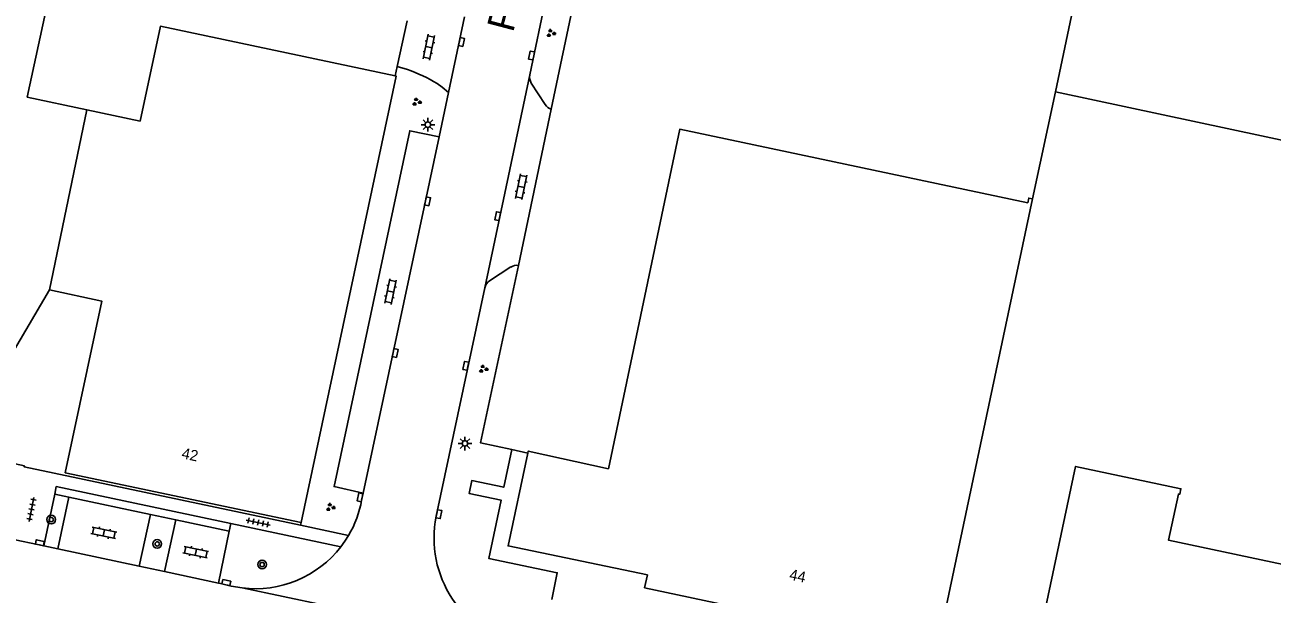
# Model space of a CAD drawing. Extents: x 131000 to 133013, y 393000 to 396501.
# Drawn here: x 131469.8 to 131584.1, y 393541.2 to 393593.5 of the extents above; entities that cross this region are included whole.
import ezdxf

# ---------------------------------------------------------------- set-up
doc = ezdxf.new("R2010")
doc.units = 0
for name, color, linetype in [('gg-afsc-hekwerk', 7, 'Continuous'), ('gg-anno-huisnummerreeks BGT', 7, 'Continuous'), ('gg-anno-openbare ruimte label', 7, 'Continuous'), ('gg-bbg-hoofdgebouw', 7, 'Continuous'), ('gg-bbg-tussenscheiding', 7, 'Continuous'), ('gg-knt-verharding', 7, 'Continuous'), ('gt-grn-groengrens', 7, 'Continuous'), ('gt-grn-vlakafsluiter', 7, 'Continuous'), ('gt-grn-weggrens', 7, 'Continuous'), ('gt-symb-boom', 7, 'Continuous'), ('gt-symb-groenvak', 7, 'Continuous'), ('gt-symb-klinker verharding', 7, 'Continuous'), ('gt-symb-kolk', 7, 'Continuous'), ('gt-symb-lichtmast', 7, 'Continuous'), ('gt-symb-tegel verharding', 7, 'Continuous')]:
    doc.layers.add(name, color=color, linetype=linetype)

# ---------------------------------------------------------------- blocks, each defined once
blk = doc.blocks.new('gt0-GRVAK')
at = {"layer": 'gt-symb-groenvak'}
for p, q in [((-0.11, 0.19), (-0.23, 0.24)), ((-0.18, 0.15), (0.09, 0.15)), ((-0.09, 0.21), (-0.16, 0.32)), ((-0.05, 0.21), (-0.05, 0.39)), ((0, 0.21), (0.06, 0.32)), ((0.02, 0.19), (0.13, 0.24)), ((0.26, -0.05), (0.2, 0.06)), ((0.31, -0.05), (0.31, 0.13)), ((0.35, -0.05), (0.41, 0.06)), ((-0.24, -0.23), (-0.36, -0.18)), ((-0.32, -0.26), (-0.05, -0.26)), ((-0.23, -0.21), (-0.29, -0.09)), ((-0.18, -0.2), (-0.18, -0.02)), ((-0.14, -0.21), (-0.07, -0.09)), ((-0.12, -0.23), (0, -0.18)), ((0.24, -0.07), (0.12, -0.02)), ((0.17, -0.11), (0.44, -0.11)), ((0.37, -0.07), (0.49, -0.02))]:
    blk.add_line(p, q, dxfattribs=at)
blk = doc.blocks.new('gt0-KOLK')
at = {"layer": 'gt-symb-kolk'}
blk.add_lwpolyline([(0, 0), (0.37, 0), (0.37, 0.4), (-0.38, 0.4), (-0.38, 0), (0, 0)], dxfattribs=at)
blk = doc.blocks.new('gt0-LMAST')
at = {"layer": 'gt-symb-lichtmast'}
for p, q in [((-0.18, 0.17), (-0.45, 0.44)), ((-0.01, 0.25), (-0.01, 0.62)), ((0.17, 0.17), (0.44, 0.44)), ((-0.26, 0), (-0.63, 0)), ((-0.18, -0.18), (-0.45, -0.45)), ((-0.01, -0.25), (-0.01, -0.63)), ((0.44, -0.45), (0.17, -0.18)), ((0.24, 0), (0.62, 0))]:
    blk.add_line(p, q, dxfattribs=at)
blk.add_circle((-0.01, 0), 0.25, dxfattribs=at)
blk = doc.blocks.new('gt0-KL1')
at = {"layer": 'gt-symb-klinker verharding'}
for p, q in [((-1.15, 0.3), (1.15, 0.3)), ((-1, -0.3), (-1, 0.3)), ((-0.5, 0.3), (-0.5, 0.45)), ((0, -0.3), (0, 0.3)), ((0.5, 0.3), (0.5, 0.45)), ((1, -0.3), (1, 0.3)), ((-1.15, -0.3), (1.15, -0.3)), ((-0.5, -0.45), (-0.5, -0.3)), ((0.5, -0.45), (0.5, -0.3))]:
    blk.add_line(p, q, dxfattribs=at)
blk = doc.blocks.new('gt0-TEG1')
at = {"layer": 'gt-symb-tegel verharding'}
for p, q in [((-1.12, 0), (1.12, 0)), ((-0.9, -0.25), (-0.9, 0.25)), ((-0.45, -0.25), (-0.45, 0.25)), ((0, -0.25), (0, 0.25)), ((0.45, -0.25), (0.45, 0.25)), ((0.9, -0.25), (0.9, 0.25))]:
    blk.add_line(p, q, dxfattribs=at)
blk = doc.blocks.new('gt0-BOOM')
at = {"layer": 'gt-symb-boom'}
for radius in [0.4, 0.2]:
    blk.add_circle((0, 0), radius, dxfattribs=at)

msp = doc.modelspace()

# ---------------------------------------------------------------- linework, layer by layer
at = {"layer": 'gg-afsc-hekwerk'}
for p, q in [((131564.26, 393587.31), (131575.24, 393639.29)), ((131520.36, 393596.75), (131518.03, 393585.72)), ((131504.83, 393593.84), (131503.91, 393589.64)), ((131503.91, 393589.64), (131503.73, 393588.78)), ((131562.17, 393577.5), (131564.26, 393587.31)), ((131564.26, 393587.31), (131605.66, 393578.49)), ((131518.03, 393585.72), (131515.04, 393571.39)), ((131514.42, 393554.48), (131515.88, 393554.16))]:
    msp.add_line(p, q, dxfattribs=at)
msp.add_lwpolyline([(131515.04, 393571.39), (131511.56, 393555.09), (131514.42, 393554.48)], dxfattribs=at)
at = {"layer": 'gg-bbg-hoofdgebouw'}
msp.add_line((131562.17, 393577.5), (131553.31, 393535.64), dxfattribs=at)
for points in [[(131442.7, 393563.3), (131445.84, 393578.11), (131446.09, 393578.06), (131450.67, 393599.78), (131471.81, 393595.3), (131470, 393586.83), (131475.45, 393585.67)], [(131475.45, 393585.67), (131480.34, 393584.63), (131482.2, 393593.34), (131503.73, 393588.78)], [(131503.73, 393588.78), (131503.81, 393588.76), (131495.1, 393547.78)], [(131562.17, 393577.5), (131561.82, 393577.57), (131561.72, 393577.14), (131529.81, 393583.88), (131523.27, 393552.72), (131515.92, 393554.34), (131515.88, 393554.16)], [(131472.02, 393569.13), (131463.41, 393554.5), (131441.8, 393559.08), (131442.7, 393563.3)], [(131495.1, 393547.78), (131473.48, 393552.36), (131476.83, 393568.11), (131472.02, 393569.13)], [(131603, 393565.57), (131592.2, 393567.86), (131592.09, 393567.36), (131592.21, 393567.34), (131587.15, 393543.5), (131574.63, 393546.16), (131575.53, 393550.4), (131575.65, 393550.38), (131575.76, 393550.89), (131566.11, 393552.93), (131562.06, 393533.86)], [(131553.24, 393535.3), (131552.9, 393535.38), (131553.07, 393536.16), (131526.6, 393541.8), (131526.85, 393542.97), (131514.08, 393545.64), (131515.88, 393554.16)]]:
    msp.add_lwpolyline(points, dxfattribs=at)
at = {"layer": 'gg-bbg-tussenscheiding'}
msp.add_line((131475.45, 393585.67), (131472.02, 393569.13), dxfattribs=at)
at = {"layer": 'gg-knt-verharding'}
for p, q in [((131517.85, 393597.35), (131516.07, 393588.87)), ((131508.61, 393587.25), (131510.08, 393594.2)), ((131504.85, 393589.37), (131503.91, 393589.64)), ((131516.07, 393588.87), (131511.94, 393569.34)), ((131516.21, 393588.12), (131517.48, 393586.15)), ((131508.61, 393587.25), (131507.75, 393583.2)), ((131507.75, 393583.2), (131500.79, 393550.49)), ((131514.34, 393571.24), (131512.38, 393569.97)), ((131511.94, 393569.34), (131507.49, 393548.36)), ((131472.51, 393550.38), (131471.51, 393545.64)), ((131472.8, 393545.37), (131473.81, 393550.11)), ((131473.81, 393550.11), (131481.28, 393548.51)), ((131500.79, 393550.49), (131500.65, 393549.84)), ((131481.28, 393548.51), (131480.26, 393543.77)), ((131482.57, 393543.28), (131483.63, 393548.03)), ((131483.63, 393548.03), (131488.5, 393546.99)), ((131488.5, 393546.99), (131487.54, 393542.23)), ((131498.76, 393545.55), (131488.65, 393547.7)), ((131499.46, 393546.6), (131495.04, 393547.53)), ((131471.51, 393545.64), (131468.32, 393546.32)), ((131471.51, 393545.64), (131472.8, 393545.37)), ((131480.26, 393543.77), (131472.8, 393545.37)), ((131480.26, 393543.77), (131482.57, 393543.28)), ((131487.54, 393542.23), (131482.57, 393543.28)), ((131487.54, 393542.23), (131487.7, 393542.2))]:
    msp.add_line(p, q, dxfattribs=at)
for points in [[(131508.61, 393587.25), (131508.02, 393587.76), (131507.58, 393588.07)], [(131500.79, 393550.49), (131498.12, 393551.09), (131505.07, 393583.75), (131507.75, 393583.2)], [(131495.04, 393547.53), (131469.71, 393552.9), (131469.73, 393553), (131441.31, 393559.05), (131442.24, 393563.41)], [(131518.1, 393540.73), (131518.58, 393543.18), (131512.32, 393544.48), (131513.44, 393549.85), (131510.5, 393550.46), (131510.75, 393551.64), (131513.68, 393551.03), (131514.42, 393554.48)], [(131488.65, 393547.7), (131472.65, 393551.08), (131472.51, 393550.38)], [(131499.46, 393546.6), (131499.12, 393546.06), (131498.76, 393545.55)], [(131489.69, 393541.78), (131488.69, 393541.95), (131487.7, 393542.2)]]:
    msp.add_lwpolyline(points, dxfattribs=at)
for centre, radius, start, end in [((131500.78, 393577.27), 12.76, 57.8161, 71.3977), ((131517.11, 393588.67), 1.06, 169.1802, 211.5901), ((131518.36, 393586.71), 1.04, 212.1748, 251.2245), ((131514.89, 393570.41), 0.991, 81.489, 123.7427), ((131512.93, 393569.12), 1.01, 123.2105, 167.7879), ((131490.88, 393551.6), 9.93, 329.7489, 349.8325), ((131517.53, 393546.39), 10.24, 168.8946, 256.8586), ((131490.93, 393551.58), 9.87, 262.8148, 322.4205)]:
    msp.add_arc(centre, radius, start, end, dxfattribs=at)
at = {"layer": 'gt-grn-groengrens'}
for p, q in [((131473.81, 393550.11), (131472.51, 393550.38)), ((131483.63, 393548.03), (131481.28, 393548.51)), ((131488.5, 393546.99), (131488.65, 393547.7))]:
    msp.add_line(p, q, dxfattribs=at)
at = {"layer": 'gt-grn-vlakafsluiter'}
msp.add_line((131495.04, 393547.53), (131495.1, 393547.78), dxfattribs=at)
at = {"layer": 'gt-grn-weggrens'}
msp.add_line((131515.21, 393536.42), (131489.69, 393541.78), dxfattribs=at)

# ---------------------------------------------------------------- block references
at = {"layer": 'gt-symb-boom'}
for p in [(131472.2, 393548.05), (131481.91, 393545.82), (131491.53, 393543.93)]:
    msp.add_blockref('gt0-BOOM', p, dxfattribs=at)
at = {"layer": 'gt-symb-groenvak'}
for p in [(131518, 393592.7), (131505.69, 393586.39), (131511.8, 393561.88), (131497.78, 393549.19)]:
    msp.add_blockref('gt0-GRVAK', p, dxfattribs=at)
at = {"layer": 'gt-symb-klinker verharding'}
for p, rotation in [((131506.82, 393591.42), 78.70129979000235), ((131515.28, 393578.61), 78.86988891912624), ((131503.3, 393568.98), 77.99329169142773), ((131477.01, 393546.84), 168.04935273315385), ((131485.44, 393545.06), 168.11724113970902)]:
    msp.add_blockref('gt0-KL1', p, dxfattribs=dict(at, rotation=rotation))
at = {"layer": 'gt-symb-kolk'}
for p, rotation in [((131509.61, 393591.93), -101.82670392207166), ((131516.43, 393590.62), 78.17329607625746), ((131506.5, 393577.31), -102.00670831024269), ((131513.32, 393575.87), 78.04935273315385), ((131503.53, 393563.38), -102.06274602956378), ((131510.4, 393562.13), 78.04935273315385), ((131500.7, 393550.07), 77.99329168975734), ((131507.54, 393548.59), -101.95064726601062), ((131471.11, 393545.73), -12.118760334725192), ((131488.21, 393542.08), -12.771242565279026)]:
    msp.add_blockref('gt0-KOLK', p, dxfattribs=dict(at, rotation=rotation))
at = {"layer": 'gt-symb-lichtmast'}
for p in [(131506.73, 393584.3), (131510.13, 393555.04)]:
    msp.add_blockref('gt0-LMAST', p, dxfattribs=at)
at = {"layer": 'gt-symb-tegel verharding'}
for p, rotation in [((131470.39, 393548.99), 78.52151796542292), ((131491.16, 393547.78), -11.950647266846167)]:
    msp.add_blockref('gt0-TEG1', p, dxfattribs=dict(at, rotation=rotation))

# ---------------------------------------------------------------- texts
at = {"layer": 'gg-anno-huisnummerreeks BGT'}
for s, p in [('42', (131484.09, 393553.69)), ('44', (131539.8, 393542.56))]:
    msp.add_text(s, height=1, rotation=348, dxfattribs=at).set_placement(p)
at = {"layer": 'gg-anno-openbare ruimte label'}
msp.add_text('Fiera', height=2.5, rotation=75.2, dxfattribs=at).set_placement((131514.53, 393592.7))

doc.saveas('drawing.dxf')
